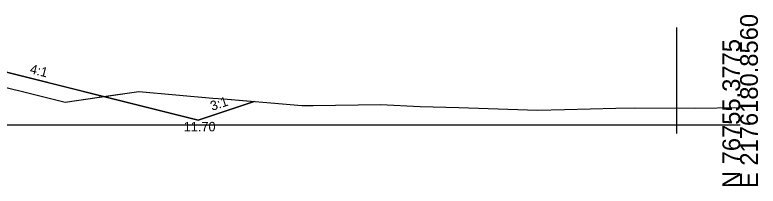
# Model space of a CAD drawing. Extents: x 2177029 to 2201446, y 59897 to 78390.
# Drawn here: x 2199328.2 to 2199445.6, y 66397.6 to 66424.6 of the extents above; entities that cross this region are included whole.
import ezdxf

# ---------------------------------------------------------------- set-up
doc = ezdxf.new("R2010")
doc.units = 0
for name, color, linetype in [('Exist Cross Section Cell', 7, 'Continuous'), ('Exist PHM Roadway Shape', 7, 'Continuous'), ('Exist XS Ground Line', 7, 'Continuous'), ('Prop CMT Guardrail Widen Shoulder', 7, 'Continuous'), ('Prop CMT Top Wall Envelope', 7, 'Continuous'), ('Prop Hatching', 7, 'Continuous'), ('Prop XS Side Slope Text', 7, 'Continuous'), ('Scratch_Level_2', 7, 'Continuous')]:
    doc.layers.add(name, color=color, linetype=linetype)

msp = doc.modelspace()

# ---------------------------------------------------------------- linework, layer by layer
at = {"layer": 'Exist Cross Section Cell'}
msp.add_line((2199242.73, 66407.31), (2199442.73, 66407.31), dxfattribs=at)
at = {"layer": 'Exist XS Ground Line'}
msp.add_lwpolyline([(2199320.71, 66414.7), (2199336.19, 66410.89), (2199337.95, 66411.15), (2199347.78, 66412.54), (2199359.49, 66411.5), (2199361.14, 66411.37), (2199368.66, 66410.75), (2199373.53, 66410.35), (2199375.31, 66410.33), (2199385.93, 66410.49), (2199392.23, 66410.19), (2199398.32, 66410.04), (2199409.15, 66409.68), (2199410.72, 66409.61), (2199414.99, 66409.73), (2199423.11, 66409.93), (2199426.07, 66409.95), (2199435.5, 66409.92), (2199442.73, 66410.03)], dxfattribs=at)
at = {"layer": 'Prop Hatching'}
msp.add_line((2199357.16, 66408.01), (2199366.02, 66410.97), dxfattribs=at)
msp.add_lwpolyline([(2199318.74, 66417.11), (2199320.74, 66417.11), (2199357.16, 66408.01)], dxfattribs=at)
at = {"layer": 'Prop XS Side Slope Text'}
for points in [[(2199336.19, 66410.89), (2199337.95, 66411.15), (2199342.21, 66411.75), (2199324.74, 66416.11), (2199319.74, 66416.11), (2199310.29, 66416.11), (2199311.96, 66416.09), (2199315.12, 66416.01), (2199317.23, 66415.47), (2199320.71, 66414.7)], [(2199347.78, 66412.54), (2199359.49, 66411.5), (2199361.14, 66411.37), (2199366.02, 66410.97), (2199357.16, 66408.01), (2199342.21, 66411.75)]]:
    msp.add_lwpolyline(points, close=True, dxfattribs=at)
at = {"layer": 'Scratch_Level_2'}
msp.add_line((2199432.73, 66405.94), (2199432.73, 66422.68), dxfattribs=at)

# ---------------------------------------------------------------- texts
at = {"layer": 'Exist Cross Section Cell'}
for s, p in [('E 2176180.8560', (2199445.53, 66397.31)), ('N 76755.3775', (2199442.73, 66397.31))]:
    msp.add_text(s, height=2.8, rotation=90, dxfattribs=at).set_placement(p)
at = {"layer": 'Exist PHM Roadway Shape'}
msp.add_text('RT_Slope_Fill', height=0.2, dxfattribs=at).set_placement((2199341.25, 66411.65))
at = {"layer": 'Prop CMT Guardrail Widen Shoulder'}
msp.add_text('4:1', height=1.5, rotation=345.9641, dxfattribs=at).set_placement((2199330.5, 66415.45))
at = {"layer": 'Prop CMT Top Wall Envelope'}
msp.add_text('3:1', height=1.5, rotation=18.4349, dxfattribs=at).set_placement((2199359.37, 66409.49))
msp.add_text('11.70', height=1.5, dxfattribs=at).set_placement((2199354.89, 66406.26))

doc.saveas('drawing.dxf')
